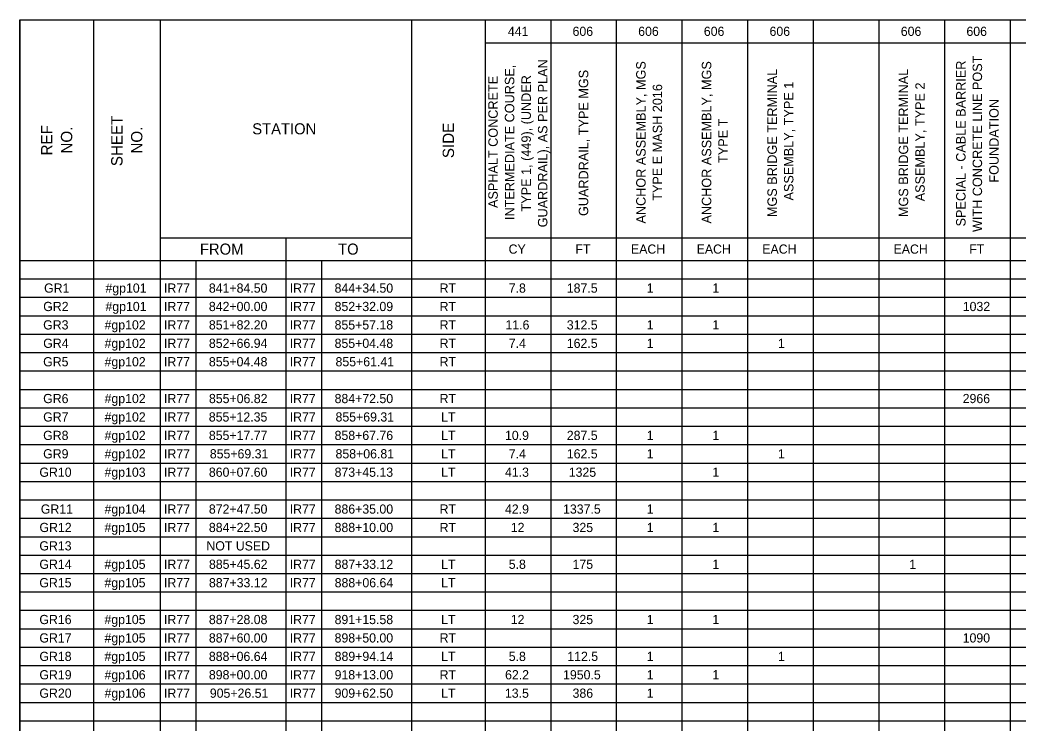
# Model space of a CAD drawing. Extents: x -542 to 295, y -281 to 32.
# Drawn here: x -16.42 to -1.5, y -90.1 to -79.59 of the extents above; entities that cross this region are included whole.
import ezdxf

# ---------------------------------------------------------------- set-up
doc = ezdxf.new("R2010")
doc.units = 0
doc.layers.add('SC_Scratch1', color=7, linetype='Continuous')
doc.layers.add('SH_Text', color=7, linetype='Continuous')

msp = doc.modelspace()

# ---------------------------------------------------------------- linework, layer by layer
at = {"layer": 'SC_Scratch1'}
msp.add_lwpolyline([(-16.421, -79.593), (14.079, -79.593), (14.079, -100.593), (-16.421, -100.593)], close=True, dxfattribs=at)
at = {"layer": 'SH_Text'}
for p, q in [((-16.421, -79.593), (14.079, -79.593)), ((-16.421, -79.593), (-16.421, -100.593)), ((-15.323, -79.593), (-15.323, -99.977)), ((-14.325, -79.593), (-14.325, -99.977)), ((-10.567, -79.593), (-10.567, -99.977)), ((-9.469, -79.593), (-9.469, -100.593)), ((-8.488, -79.593), (-8.488, -100.593)), ((-7.507, -79.593), (-7.507, -100.593)), ((-6.526, -79.593), (-6.526, -100.593)), ((-5.545, -79.593), (-5.545, -100.593)), ((-4.563, -79.593), (-4.563, -100.593)), ((-3.582, -79.593), (-3.582, -100.593)), ((-2.601, -79.593), (-2.601, -100.593)), ((-1.62, -79.593), (-1.62, -100.593)), ((-9.469, -79.933), (14.079, -79.933)), ((-14.325, -82.847), (-10.567, -82.847)), ((-12.446, -82.847), (-12.446, -99.977)), ((-9.469, -82.847), (14.079, -82.847)), ((-16.421, -83.187), (14.079, -83.187)), ((-13.793, -83.187), (-13.793, -99.977)), ((-11.914, -83.187), (-11.914, -99.977)), ((-16.421, -83.462), (14.079, -83.462)), ((-16.421, -83.737), (14.079, -83.737)), ((-16.421, -84.013), (14.079, -84.013)), ((-16.421, -84.288), (14.079, -84.288)), ((-16.421, -84.563), (14.079, -84.563)), ((-16.421, -84.838), (14.079, -84.838)), ((-16.421, -85.114), (14.079, -85.114)), ((-16.421, -85.389), (14.079, -85.389)), ((-16.421, -85.664), (14.079, -85.664)), ((-16.421, -85.94), (14.079, -85.94)), ((-16.421, -86.215), (14.079, -86.215)), ((-16.421, -86.49), (14.079, -86.49)), ((-16.421, -86.765), (14.079, -86.765)), ((-16.421, -87.041), (14.079, -87.041)), ((-16.421, -87.316), (14.079, -87.316)), ((-16.421, -87.591), (14.079, -87.591)), ((-16.421, -87.866), (14.079, -87.866)), ((-16.421, -88.142), (14.079, -88.142)), ((-16.421, -88.417), (14.079, -88.417)), ((-16.421, -88.692), (14.079, -88.692)), ((-16.421, -88.967), (14.079, -88.967)), ((-16.421, -89.243), (14.079, -89.243)), ((-16.421, -89.518), (14.079, -89.518)), ((-16.421, -89.793), (14.079, -89.793)), ((-16.421, -90.068), (14.079, -90.068))]:
    msp.add_line(p, q, dxfattribs=at)

# ---------------------------------------------------------------- texts
for s, height, p in [('441', 0.1376, (-9.128, -79.831)), ('606', 0.1376, (-8.161, -79.831)), ('606', 0.1376, (-7.18, -79.831)), ('606', 0.1376, (-6.199, -79.831)), ('606', 0.1376, (-5.217, -79.831)), ('606', 0.1376, (-3.255, -79.831)), ('606', 0.1376, (-2.274, -79.831)), ('STATION', 0.1652, (-12.949, -81.302)), ('FROM', 0.1652, (-13.731, -83.1)), ('TO', 0.1652, (-11.666, -83.1)), ('CY', 0.1376, (-9.117, -83.086)), ('FT', 0.1376, (-8.118, -83.086)), ('EACH', 0.1376, (-7.288, -83.086)), ('EACH', 0.1376, (-6.306, -83.086)), ('EACH', 0.1376, (-5.325, -83.086)), ('EACH', 0.1376, (-3.363, -83.086)), ('FT', 0.1376, (-2.231, -83.086)), ('GR1', 0.1376, (-16.06, -83.669)), ('#gp101', 0.1376, (-15.143, -83.669)), ('IR77', 0.1376, (-14.268, -83.669)), ('841+84.50', 0.1376, (-13.597, -83.669)), ('IR77', 0.1376, (-12.389, -83.669)), ('844+34.50', 0.1376, (-11.718, -83.669)), ('RT', 0.1376, (-10.148, -83.669)), ('7.8', 0.1376, (-9.115, -83.669)), ('187.5', 0.1376, (-8.247, -83.669)), ('1', 0.138, (-7.053, -83.669)), ('1', 0.138, (-6.072, -83.669)), ('GR2', 0.1376, (-16.073, -83.944)), ('#gp101', 0.1376, (-15.143, -83.944)), ('IR77', 0.1376, (-14.268, -83.944)), ('842+00.00', 0.1376, (-13.597, -83.944)), ('IR77', 0.1376, (-12.389, -83.944)), ('852+32.09', 0.1376, (-11.718, -83.944)), ('RT', 0.1376, (-10.148, -83.944)), ('1032', 0.1376, (-2.329, -83.944)), ('GR3', 0.1376, (-16.074, -84.219)), ('#gp102', 0.1376, (-15.156, -84.219)), ('IR77', 0.1376, (-14.268, -84.219)), ('851+82.20', 0.1376, (-13.597, -84.219)), ('IR77', 0.1376, (-12.389, -84.219)), ('855+57.18', 0.1376, (-11.718, -84.219)), ('RT', 0.1376, (-10.148, -84.219)), ('11.6', 0.1376, (-9.164, -84.219)), ('312.5', 0.1376, (-8.247, -84.219)), ('1', 0.138, (-7.053, -84.219)), ('1', 0.138, (-6.072, -84.219)), ('GR4', 0.1376, (-16.073, -84.494)), ('#gp102', 0.1376, (-15.156, -84.494)), ('IR77', 0.1376, (-14.268, -84.494)), ('852+66.94', 0.1376, (-13.597, -84.494)), ('IR77', 0.1376, (-12.389, -84.494)), ('855+04.48', 0.1376, (-11.718, -84.494)), ('RT', 0.1376, (-10.148, -84.494)), ('7.4', 0.1376, (-9.114, -84.494)), ('162.5', 0.1376, (-8.247, -84.494)), ('1', 0.138, (-7.053, -84.494)), ('1', 0.138, (-5.091, -84.494)), ('GR5', 0.1376, (-16.074, -84.77)), ('#gp102', 0.1376, (-15.156, -84.77)), ('IR77', 0.1376, (-14.268, -84.77)), ('855+04.48', 0.1376, (-13.597, -84.77)), ('IR77', 0.1376, (-12.389, -84.77)), ('855+61.41', 0.1376, (-11.704, -84.77)), ('RT', 0.1376, (-10.148, -84.77)), ('GR6', 0.1376, (-16.074, -85.32)), ('#gp102', 0.1376, (-15.156, -85.32)), ('IR77', 0.1376, (-14.268, -85.32)), ('855+06.82', 0.1376, (-13.596, -85.32)), ('IR77', 0.1376, (-12.389, -85.32)), ('884+72.50', 0.1376, (-11.718, -85.32)), ('RT', 0.1376, (-10.148, -85.32)), ('2966', 0.1376, (-2.33, -85.32)), ('GR7', 0.1376, (-16.074, -85.595)), ('#gp102', 0.1376, (-15.156, -85.595)), ('IR77', 0.1376, (-14.268, -85.595)), ('855+12.35', 0.1376, (-13.598, -85.595)), ('IR77', 0.1376, (-12.389, -85.595)), ('855+69.31', 0.1376, (-11.704, -85.595)), ('LT', 0.1376, (-10.126, -85.595)), ('GR8', 0.1376, (-16.074, -85.871)), ('#gp102', 0.1376, (-15.156, -85.871)), ('IR77', 0.1376, (-14.268, -85.871)), ('855+17.77', 0.1376, (-13.597, -85.871)), ('IR77', 0.1376, (-12.389, -85.871)), ('858+67.76', 0.1376, (-11.718, -85.871)), ('LT', 0.1376, (-10.126, -85.871)), ('10.9', 0.1376, (-9.171, -85.871)), ('287.5', 0.1376, (-8.247, -85.871)), ('1', 0.138, (-7.053, -85.871)), ('1', 0.138, (-6.072, -85.871)), ('GR9', 0.1376, (-16.074, -86.146)), ('#gp102', 0.1376, (-15.156, -86.146)), ('IR77', 0.1376, (-14.268, -86.146)), ('855+69.31', 0.1376, (-13.583, -86.146)), ('IR77', 0.1376, (-12.389, -86.146)), ('858+06.81', 0.1376, (-11.704, -86.146)), ('LT', 0.1376, (-10.126, -86.146)), ('7.4', 0.1376, (-9.114, -86.146)), ('162.5', 0.1376, (-8.247, -86.146)), ('1', 0.138, (-7.053, -86.146)), ('1', 0.138, (-5.091, -86.146)), ('GR10', 0.1376, (-16.13, -86.421)), ('#gp103', 0.1376, (-15.157, -86.421)), ('IR77', 0.1376, (-14.268, -86.421)), ('860+07.60', 0.1376, (-13.597, -86.421)), ('IR77', 0.1376, (-12.389, -86.421)), ('873+45.13', 0.1376, (-11.718, -86.421)), ('LT', 0.1376, (-10.126, -86.421)), ('41.3', 0.1376, (-9.171, -86.421)), ('1325', 0.1376, (-8.218, -86.421)), ('1', 0.138, (-6.072, -86.421)), ('GR11', 0.1376, (-16.109, -86.972)), ('#gp104', 0.1376, (-15.157, -86.972)), ('IR77', 0.1376, (-14.268, -86.972)), ('872+47.50', 0.1376, (-13.597, -86.972)), ('IR77', 0.1376, (-12.389, -86.972)), ('886+35.00', 0.1376, (-11.718, -86.972)), ('RT', 0.1376, (-10.148, -86.972)), ('42.9', 0.1376, (-9.171, -86.972)), ('1337.5', 0.1376, (-8.303, -86.972)), ('1', 0.138, (-7.053, -86.972)), ('GR12', 0.1376, (-16.129, -87.247)), ('#gp105', 0.1376, (-15.158, -87.247)), ('IR77', 0.1376, (-14.268, -87.247)), ('884+22.50', 0.1376, (-13.597, -87.247)), ('IR77', 0.1376, (-12.389, -87.247)), ('888+10.00', 0.1376, (-11.718, -87.247)), ('RT', 0.1376, (-10.148, -87.247)), ('12', 0.1376, (-9.085, -87.247)), ('325', 0.1376, (-8.161, -87.247)), ('1', 0.138, (-7.053, -87.247)), ('1', 0.138, (-6.072, -87.247)), ('GR13', 0.1376, (-16.13, -87.522)), ('NOT USED', 0.1376, (-13.634, -87.522)), ('GR14', 0.1376, (-16.13, -87.797)), ('#gp105', 0.1376, (-15.158, -87.797)), ('IR77', 0.1376, (-14.268, -87.797)), ('885+45.62', 0.1376, (-13.596, -87.797)), ('IR77', 0.1376, (-12.389, -87.797)), ('887+33.12', 0.1376, (-11.717, -87.797)), ('LT', 0.1376, (-10.126, -87.797)), ('5.8', 0.1376, (-9.115, -87.797)), ('175', 0.1376, (-8.161, -87.797)), ('1', 0.138, (-6.072, -87.797)), ('1', 0.138, (-3.128, -87.797)), ('GR15', 0.1376, (-16.131, -88.073)), ('#gp105', 0.1376, (-15.158, -88.073)), ('IR77', 0.1376, (-14.268, -88.073)), ('887+33.12', 0.1376, (-13.596, -88.073)), ('IR77', 0.1376, (-12.389, -88.073)), ('888+06.64', 0.1376, (-11.717, -88.073)), ('LT', 0.1376, (-10.126, -88.073)), ('GR16', 0.1376, (-16.13, -88.623)), ('#gp105', 0.1376, (-15.158, -88.623)), ('IR77', 0.1376, (-14.268, -88.623)), ('887+28.08', 0.1376, (-13.597, -88.623)), ('IR77', 0.1376, (-12.389, -88.623)), ('891+15.58', 0.1376, (-11.718, -88.623)), ('LT', 0.1376, (-10.126, -88.623)), ('12', 0.1376, (-9.085, -88.623)), ('325', 0.1376, (-8.161, -88.623)), ('1', 0.138, (-7.053, -88.623)), ('1', 0.138, (-6.072, -88.623)), ('GR17', 0.1376, (-16.13, -88.898)), ('#gp105', 0.1376, (-15.158, -88.898)), ('IR77', 0.1376, (-14.268, -88.898)), ('887+60.00', 0.1376, (-13.597, -88.898)), ('IR77', 0.1376, (-12.389, -88.898)), ('898+50.00', 0.1376, (-11.718, -88.898)), ('RT', 0.1376, (-10.148, -88.898)), ('1090', 0.1376, (-2.33, -88.898)), ('GR18', 0.1376, (-16.13, -89.174)), ('#gp105', 0.1376, (-15.158, -89.174)), ('IR77', 0.1376, (-14.268, -89.174)), ('888+06.64', 0.1376, (-13.597, -89.174)), ('IR77', 0.1376, (-12.389, -89.174)), ('889+94.14', 0.1376, (-11.717, -89.174)), ('LT', 0.1376, (-10.126, -89.174)), ('5.8', 0.1376, (-9.115, -89.174)), ('112.5', 0.1376, (-8.24, -89.174)), ('1', 0.138, (-7.053, -89.174)), ('1', 0.138, (-5.091, -89.174)), ('GR19', 0.1376, (-16.13, -89.449)), ('#gp106', 0.1376, (-15.157, -89.449)), ('IR77', 0.1376, (-14.268, -89.449)), ('898+00.00', 0.1376, (-13.597, -89.449)), ('IR77', 0.1376, (-12.389, -89.449)), ('918+13.00', 0.1376, (-11.718, -89.449)), ('RT', 0.1376, (-10.148, -89.449)), ('62.2', 0.1376, (-9.17, -89.449)), ('1950.5', 0.1376, (-8.303, -89.449)), ('1', 0.138, (-7.053, -89.449)), ('1', 0.138, (-6.072, -89.449)), ('GR20', 0.1376, (-16.13, -89.724)), ('#gp106', 0.1376, (-15.157, -89.724)), ('IR77', 0.1376, (-14.268, -89.724)), ('905+26.51', 0.1376, (-13.583, -89.724)), ('IR77', 0.1376, (-12.389, -89.724)), ('909+62.50', 0.1376, (-11.718, -89.724)), ('LT', 0.1376, (-10.126, -89.724)), ('13.5', 0.1376, (-9.172, -89.724)), ('386', 0.1376, (-8.161, -89.724)), ('1', 0.138, (-7.053, -89.724))]:
    msp.add_text(s, height=height, dxfattribs=at).set_placement(p)
for s, height, p in [('GUARDRAIL), AS PER PLAN', 0.14136, (-8.537, -82.692)), ('ANCHOR ASSEMBLY, MGS ', 0.14136, (-7.069, -82.635)), ('ANCHOR ASSEMBLY, MGS ', 0.14136, (-6.088, -82.635)), ('SPECIAL - CABLE BARRIER ', 0.14136, (-2.287, -82.679)), ('WITH CONCRETE LINE POST ', 0.14136, (-2.04, -82.762)), ('INTERMEDIATE COURSE, ', 0.14136, (-9.032, -82.583)), ('GUARDRAIL, TYPE MGS', 0.14136, (-7.927, -82.523)), ('MGS BRIDGE TERMINAL ', 0.14136, (-5.107, -82.539)), ('MGS BRIDGE TERMINAL ', 0.14136, (-3.145, -82.539)), ('ASPHALT CONCRETE ', 0.14136, (-9.279, -82.403)), ('TYPE 1, (449), (UNDER ', 0.14136, (-8.784, -82.455)), ('ASSEMBLY, TYPE 1', 0.14136, (-4.86, -82.291)), ('ASSEMBLY, TYPE 2', 0.14136, (-2.897, -82.303)), ('TYPE E MASH 2016', 0.14136, (-6.822, -82.295)), ('FOUNDATION', 0.1414, (-1.792, -82.024)), ('SHEET', 0.1696, (-14.888, -81.778)), ('SIDE', 0.1696, (-9.933, -81.658)), ('TYPE T', 0.1414, (-5.841, -81.73)), ('REF', 0.1696, (-15.936, -81.618)), ('NO.', 0.1696, (-15.639, -81.59)), ('NO.', 0.1696, (-14.591, -81.59))]:
    msp.add_text(s, height=height, rotation=90, dxfattribs=at).set_placement(p)

doc.saveas('drawing.dxf')
